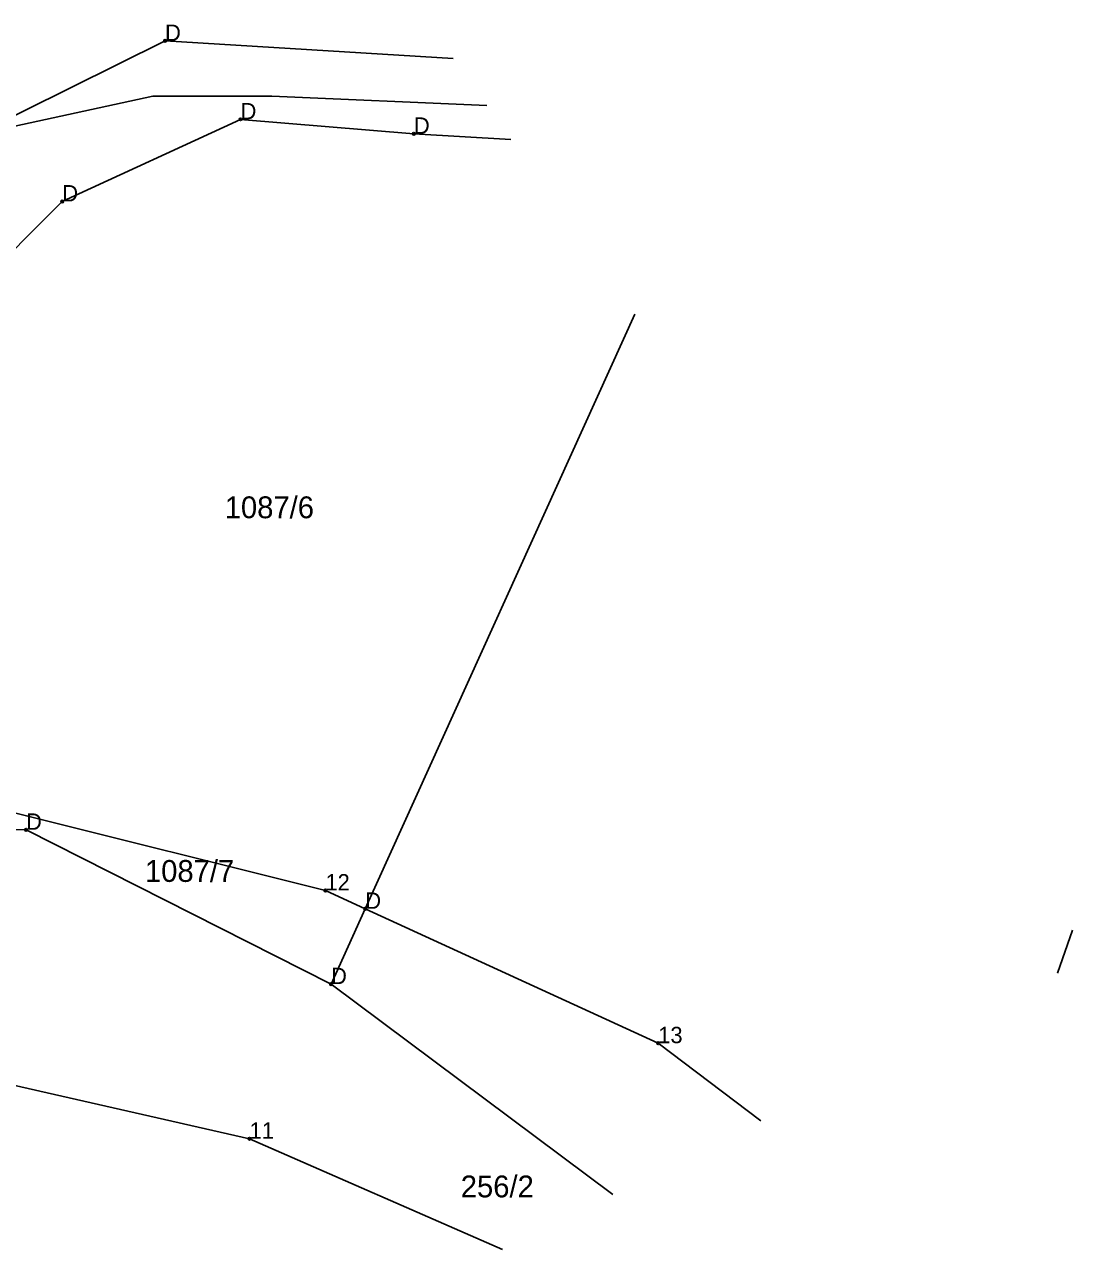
# Model space of a CAD drawing. Extents: x 7467189 to 7469366, y 5491487 to 5492734.
# Drawn here: x 7469294.1 to 7469366.1, y 5491629 to 5491713.2 of the extents above; entities that cross this region are included whole.
import ezdxf

# ---------------------------------------------------------------- set-up
doc = ezdxf.new("R2010")
doc.units = 0
for name, color, linetype in [('203-punkt graniczny', 7, 'Continuous'), ('203-punkt graniczny-Atr103', 7, 'Continuous'), ('211-numer działki ewidencyjnej', 7, 'Continuous'), ('217-kontur klasyfikacyjny', 7, 'Continuous'), ('218-kontur użytku gruntowego', 7, 'Continuous'), ('219-działka ewidencyjna', 7, 'Continuous')]:
    doc.layers.add(name, color=color, linetype=linetype)

# ---------------------------------------------------------------- blocks, each defined once
blk = doc.blocks.new('203')
blk.add_circle((0, 0), 0.09)

msp = doc.modelspace()

# ---------------------------------------------------------------- linework, layer by layer
at = {"layer": '217-kontur klasyfikacyjny'}
for points in [[(7469290.79, 5491705.65), (7469302.93, 5491708.28)], [(7469302.93, 5491708.28), (7469311.1, 5491708.28)], [(7469311.1, 5491708.28), (7469325.874, 5491707.638)], [(7469336.06, 5491693.299), (7469317.53, 5491652.45)], [(7469269.64, 5491658.43), (7469294.22, 5491657.88)], [(7469294.22, 5491657.88), (7469315.18, 5491647.28)], [(7469315.18, 5491647.28), (7469317.53, 5491652.45)], [(7469317.53, 5491652.45), (7469337.66, 5491643.22)], [(7469337.66, 5491643.22), (7469344.712, 5491637.885)]]:
    msp.add_lwpolyline(points, dxfattribs=at)
at = {"layer": '218-kontur użytku gruntowego'}
for points in [[(7469290.79, 5491705.65), (7469302.93, 5491708.28)], [(7469302.93, 5491708.28), (7469311.1, 5491708.28)], [(7469311.1, 5491708.28), (7469325.874, 5491707.638)], [(7469336.06, 5491693.299), (7469317.53, 5491652.45)], [(7469294.22, 5491657.88), (7469269.64, 5491658.43)], [(7469315.18, 5491647.28), (7469294.22, 5491657.88)], [(7469317.53, 5491652.45), (7469315.18, 5491647.28)], [(7469337.66, 5491643.22), (7469317.53, 5491652.45)], [(7469334.541, 5491632.824), (7469315.18, 5491647.28)], [(7469344.712, 5491637.885), (7469337.66, 5491643.22)], [(7469290.31, 5491641.02), (7469309.58, 5491636.66)], [(7469309.58, 5491636.66), (7469326.955, 5491629.049)]]:
    msp.add_lwpolyline(points, dxfattribs=at)
at = {"layer": '219-działka ewidencyjna'}
for points in [[(7469290.79, 5491705.65), (7469303.77, 5491712.07)], [(7469303.77, 5491712.07), (7469323.577, 5491710.87)], [(7469296.71, 5491701.04), (7469308.96, 5491706.68)], [(7469308.96, 5491706.68), (7469320.87, 5491705.69)], [(7469320.87, 5491705.69), (7469327.539, 5491705.294)], [(7469284.94, 5491689.24), (7469296.71, 5491701.04)], [(7469317.53, 5491652.45), (7469336.06, 5491693.299)], [(7469293.33, 5491659.07), (7469314.79, 5491653.71)], [(7469269.64, 5491658.43), (7469294.22, 5491657.88)], [(7469294.22, 5491657.88), (7469315.18, 5491647.28)], [(7469314.79, 5491653.71), (7469317.53, 5491652.45)], [(7469315.18, 5491647.28), (7469317.53, 5491652.45)], [(7469317.53, 5491652.45), (7469337.66, 5491643.22)], [(7469365.094, 5491648.026), (7469366.125, 5491650.979)], [(7469315.18, 5491647.28), (7469334.541, 5491632.824)], [(7469337.66, 5491643.22), (7469344.712, 5491637.885)], [(7469290.31, 5491641.02), (7469309.58, 5491636.66)], [(7469309.58, 5491636.66), (7469326.955, 5491629.049)]]:
    msp.add_lwpolyline(points, dxfattribs=at)

# ---------------------------------------------------------------- block references
at = {"layer": '203-punkt graniczny'}
for p in [(7469303.77, 5491712.07), (7469308.96, 5491706.68), (7469320.87, 5491705.69), (7469296.71, 5491701.04), (7469294.22, 5491657.88), (7469314.79, 5491653.71), (7469317.53, 5491652.45), (7469315.18, 5491647.28), (7469337.66, 5491643.22), (7469309.58, 5491636.66)]:
    msp.add_blockref('203', p, dxfattribs=at)

# ---------------------------------------------------------------- texts
at = {"layer": '203-punkt graniczny-Atr103'}
for s, p in [('D', (7469303.77, 5491712.07)), ('D', (7469308.96, 5491706.68)), ('D', (7469320.87, 5491705.69)), ('D', (7469296.71, 5491701.04)), ('D', (7469294.22, 5491657.88)), ('12', (7469314.79, 5491653.71)), ('D', (7469317.53, 5491652.45)), ('D', (7469315.18, 5491647.28)), ('13', (7469337.66, 5491643.22)), ('11', (7469309.58, 5491636.66))]:
    msp.add_text(s, height=1.125, dxfattribs=at).set_placement(p)
at = {"layer": '211-numer działki ewidencyjnej'}
for s, p in [('1087/6', (7469307.87, 5491679.28)), ('1087/7', (7469302.39, 5491654.3)), ('256/2', (7469324.09, 5491632.63))]:
    msp.add_text(s, height=1.5, dxfattribs=at).set_placement(p)

doc.saveas('drawing.dxf')
